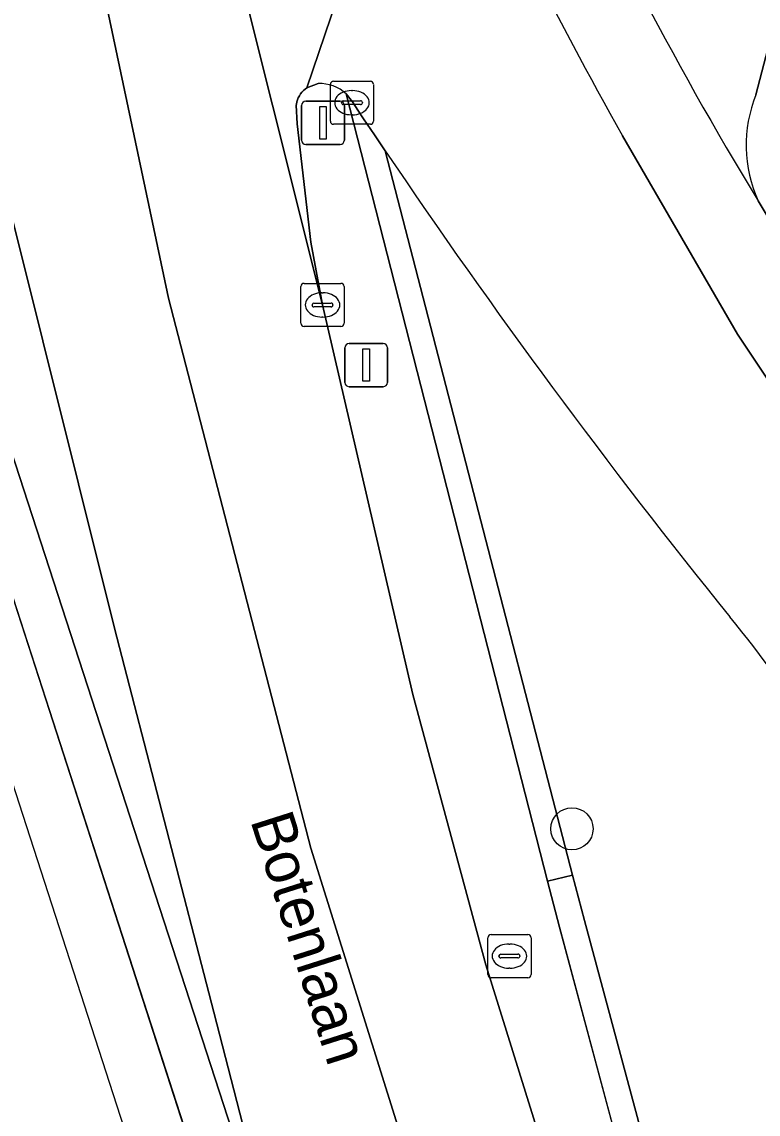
# Model space of a CAD drawing. Extents: x 159371 to 159986, y 382987 to 383597.
# Drawn here: x 159398.33 to 159415.41, y 383308.31 to 383333.62 of the extents above; entities that cross this region are included whole.
import ezdxf

# ---------------------------------------------------------------- set-up
doc = ezdxf.new("R2010")
doc.units = 0
for name, color, linetype in [('IMGEO_Berm_groen', 7, 'Continuous'), ('IMGEO_Boom', 7, 'Continuous'), ('IMGEO_Fietspad_open', 7, 'Continuous'), ('IMGEO_Groenvoorziening', 7, 'Continuous'), ('IMGEO_Haag', 7, 'Continuous'), ('IMGEO_Kolk', 7, 'Continuous'), ('IMGEO_Lichtmast', 7, 'Continuous'), ('IMGEO_Openbare_ruimte_label', 7, 'Continuous'), ('IMGEO_Rijbaan_lokaal_open', 7, 'Continuous'), ('IMGEO_Rijbaan_regionaal_gesloten', 7, 'Continuous'), ('IMGEO_Rioolput', 7, 'Continuous'), ('IMGEO_Verkeersbordpaal', 7, 'Continuous'), ('IMGEO_Verkeerseiland_gesloten', 7, 'Continuous'), ('IMGEO_Verkeerseiland_groen', 7, 'Continuous')]:
    doc.layers.add(name, color=color, linetype=linetype)

msp = doc.modelspace()

# ---------------------------------------------------------------- linework, layer by layer
at = {"layer": 'IMGEO_Berm_groen'}
for points in [[(159405.206, 383332.192), (159404.942, 383332.097), (159404.901, 383332.066), (159404.863, 383332.032), (159404.828, 383331.995), (159404.796, 383331.954), (159404.768, 383331.911), (159404.744, 383331.866), (159404.725, 383331.818), (159404.709, 383331.769), (159404.698, 383331.719), (159404.694, 383331.691), (159404.715, 383331.26), (159405.034, 383328.516), (159405.305, 383327.063), (159407.402, 383318.032), (159409.091, 383311.769), (159411.115, 383305.269), (159412.518, 383300.689), (159415.124, 383292.413), (159421.088, 383273.781)], [(159435.017, 383236.267), (159430.413, 383250.521), (159413.5, 383303.035), (159412.414, 383306.629), (159410.796, 383312.64), (159410.522, 383313.711), (159405.852, 383331.954)], [(159406.761, 383330.631), (159408.577, 383323.612), (159411.104, 383313.847), (159411.376, 383312.794), (159412.992, 383306.793), (159414.072, 383303.213), (159430.983, 383250.705), (159435.589, 383236.441), (159472.722, 383122.014), (159492.238, 383063.663), (159493.793, 383059.366), (159494.626, 383071.478), (159494.813, 383074.201), (159494.983, 383076.684), (159494.993, 383077.003)]]:
    msp.add_lwpolyline(points, dxfattribs=at)
for centre, radius, start, end in [((159405.255, 383331.329), 0.864, 46.3029, 93.2474), ((159540.355, 383421.071), 161.328, 214.09704, 218.86798), ((159394.275, 383302.805), 26.627, 24.4699, 39.7553)]:
    msp.add_arc(centre, radius, start, end, dxfattribs=at)
at = {"layer": 'IMGEO_Boom'}
msp.add_circle((159411.088, 383314.922), 0.489, dxfattribs=at)
at = {"layer": 'IMGEO_Fietspad_open'}
for points in [[(159412.263, 383330.985), (159414.927, 383326.382), (159415.744, 383325.156), (159419.36, 383320.289), (159420.855, 383318.04)], [(159422.415, 383319.283), (159417.233, 383326.485), (159417.087, 383326.688), (159415.406, 383329.473)]]:
    msp.add_lwpolyline(points, dxfattribs=at)
for centre, radius, start, end in [((159489.397, 383374.406), 86.566, 203.62917, 211.26927), ((159487.582, 383373.724), 86.6, 203.26224, 209.57217)]:
    msp.add_arc(centre, radius, start, end, dxfattribs=at)
at = {"layer": 'IMGEO_Groenvoorziening'}
for points in [[(159406.761, 383330.631), (159406.509, 383331.005), (159406.258, 383331.379), (159406.127, 383331.575), (159405.997, 383331.771), (159405.852, 383331.954), (159410.522, 383313.711), (159411.104, 383313.847), (159408.577, 383323.612)], [(159472.722, 383122.014), (159435.589, 383236.441), (159430.983, 383250.705), (159414.072, 383303.213), (159412.992, 383306.793), (159411.376, 383312.794), (159411.104, 383313.847), (159410.522, 383313.711), (159410.796, 383312.64), (159412.414, 383306.629), (159413.5, 383303.035), (159430.413, 383250.521), (159435.017, 383236.267), (159472.152, 383121.826), (159491.672, 383063.465), (159493.69, 383057.889), (159493.717, 383058.243), (159493.743, 383058.624), (159493.793, 383059.366), (159492.238, 383063.663)]]:
    msp.add_lwpolyline(points, close=True, dxfattribs=at)
at = {"layer": 'IMGEO_Haag'}
for points in [[(159408.577, 383323.612), (159406.761, 383330.631), (159406.509, 383331.005), (159406.258, 383331.379), (159406.127, 383331.575), (159405.997, 383331.771), (159405.852, 383331.954), (159410.522, 383313.711), (159411.104, 383313.847)], [(159430.983, 383250.705), (159414.072, 383303.213), (159412.992, 383306.793), (159411.376, 383312.794), (159411.104, 383313.847), (159410.522, 383313.711), (159410.796, 383312.64), (159412.414, 383306.629), (159413.5, 383303.035), (159430.413, 383250.521), (159435.017, 383236.267), (159472.152, 383121.826), (159491.672, 383063.465), (159493.69, 383057.889), (159493.717, 383058.243), (159493.743, 383058.624), (159493.793, 383059.366), (159492.238, 383063.663), (159472.722, 383122.014), (159435.589, 383236.441)]]:
    msp.add_lwpolyline(points, close=True, dxfattribs=at)
at = {"layer": 'IMGEO_Kolk'}
for p, q in [((159405.487, 383331.324), (159405.487, 383332.176)), ((159405.562, 383332.25), (159406.414, 383332.25)), ((159406.488, 383332.176), (159406.488, 383331.324)), ((159405.975, 383332.03), (159406, 383332.03)), ((159405.746, 383331.744), (159405.746, 383331.756)), ((159406.184, 383331.707), (159405.786, 383331.707)), ((159405.789, 383331.793), (159406.187, 383331.793)), ((159406.23, 383331.756), (159406.23, 383331.744)), ((159405.998, 383331.47), (159405.973, 383331.47)), ((159406.414, 383331.25), (159405.562, 383331.25)), ((159404.88, 383327.563), (159405.732, 383327.563)), ((159404.805, 383326.637), (159404.805, 383327.489)), ((159405.293, 383327.343), (159405.318, 383327.343)), ((159405.806, 383327.489), (159405.806, 383326.637)), ((159405.064, 383327.057), (159405.064, 383327.069)), ((159405.107, 383327.106), (159405.505, 383327.106)), ((159405.548, 383327.069), (159405.548, 383327.057)), ((159405.502, 383327.02), (159405.104, 383327.02)), ((159405.732, 383326.563), (159404.88, 383326.563)), ((159405.316, 383326.783), (159405.291, 383326.783))]:
    msp.add_line(p, q, dxfattribs=at)
for points in [[(159405.487, 383331.324), (159405.487, 383332.176)], [(159405.562, 383332.25), (159406.414, 383332.25)], [(159406.488, 383332.176), (159406.488, 383331.324)], [(159406.414, 383331.25), (159405.562, 383331.25)], [(159404.88, 383327.563), (159405.732, 383327.563)], [(159404.805, 383326.637), (159404.805, 383327.489)], [(159405.806, 383327.489), (159405.806, 383326.637)], [(159405.732, 383326.563), (159404.88, 383326.563)]]:
    msp.add_lwpolyline(points, dxfattribs=at)
for centre, radius, start, end in [((159405.564, 383332.174), 0.0765, 91.552, 178.448), ((159405.564, 383332.174), 0.0765, 91.552, 178.448), ((159406.412, 383332.174), 0.0765, 1.552, 88.448), ((159406.412, 383332.174), 0.0765, 1.552, 88.448), ((159405.786, 383331.753), 0.0403, 85.8775, 175.7526), ((159405.783, 383331.743), 0.0366, 178.938, 274.7102), ((159406.187, 383331.75), 0.043, 264.8664, 352.4533), ((159406.191, 383331.755), 0.0386, 1.7309, 96.639), ((159405.564, 383331.326), 0.0765, 181.552, 268.448), ((159405.564, 383331.326), 0.0765, 181.552, 268.448), ((159406.412, 383331.326), 0.0765, 271.552, 358.448), ((159406.412, 383331.326), 0.0765, 271.552, 358.448), ((159404.882, 383327.487), 0.0765, 91.552, 178.448), ((159404.882, 383327.487), 0.0765, 91.552, 178.448), ((159405.73, 383327.487), 0.0765, 1.552, 88.448), ((159405.73, 383327.487), 0.0765, 1.552, 88.448), ((159405.104, 383327.066), 0.0403, 85.8775, 175.7526), ((159405.101, 383327.056), 0.0366, 178.938, 274.7102), ((159405.505, 383327.063), 0.043, 264.8664, 352.4533), ((159405.509, 383327.068), 0.0386, 1.7309, 96.639), ((159404.882, 383326.639), 0.0765, 181.552, 268.448), ((159404.882, 383326.639), 0.0765, 181.552, 268.448), ((159405.73, 383326.639), 0.0765, 271.552, 358.448), ((159405.73, 383326.639), 0.0765, 271.552, 358.448)]:
    msp.add_arc(centre, radius, start, end, dxfattribs=at)
for centre, major_axis, ratio, start_param, end_param in [((159405.974, 383331.75), (-0.387, 0.002), 0.722429, 4.712389, 7.853982), ((159405.999, 383331.75), (-0.39, 0.002), 0.717154, 1.570796, 4.712389), ((159405.292, 383327.063), (-0.387, 0.002), 0.722429, 4.712389, 7.853982), ((159405.317, 383327.063), (-0.39, 0.002), 0.717154, 1.570796, 4.712389)]:
    msp.add_ellipse(centre, major_axis=major_axis, ratio=ratio, start_param=start_param, end_param=end_param, dxfattribs=at)
at = {"layer": 'IMGEO_Lichtmast'}
for p, q in [((159405.822, 383325.269), (159405.822, 383326.069)), ((159405.822, 383326.069), (159405.822, 383325.269)), ((159405.922, 383326.169), (159406.712, 383326.169)), ((159406.712, 383326.169), (159405.922, 383326.169)), ((159406.812, 383326.069), (159406.812, 383325.269)), ((159406.812, 383325.269), (159406.812, 383326.069)), ((159406.712, 383325.169), (159405.922, 383325.169)), ((159405.922, 383325.169), (159406.712, 383325.169))]:
    msp.add_line(p, q, dxfattribs=at)
msp.add_lwpolyline([(159406.242, 383326.044), (159406.392, 383326.044), (159406.392, 383325.294), (159406.242, 383325.294), (159406.242, 383326.044)], dxfattribs=at)
for centre, start, end in [((159405.922, 383326.069), 90, 180), ((159405.922, 383326.069), 90, 180), ((159406.712, 383326.069), 0, 90), ((159406.712, 383326.069), 360, 90), ((159405.922, 383325.269), 180, 270), ((159405.922, 383325.269), 180, 270), ((159406.712, 383325.269), 270, 0), ((159406.712, 383325.269), 270, 0)]:
    msp.add_arc(centre, 0.1, start, end, dxfattribs=at)
at = {"layer": 'IMGEO_Rijbaan_lokaal_open'}
for points in [[(159407.29, 383339.017), (159404.942, 383332.097), (159405.206, 383332.192)], [(159415.352, 383331.935), (159415.872, 383333.917)], [(159405.852, 383331.954), (159405.997, 383331.771), (159406.127, 383331.575), (159406.258, 383331.379), (159406.509, 383331.005), (159406.761, 383330.631)], [(159420.855, 383318.04), (159419.36, 383320.289), (159415.744, 383325.156), (159414.927, 383326.382), (159412.263, 383330.985)]]:
    msp.add_lwpolyline(points, dxfattribs=at)
for centre, radius, start, end in [((159489.397, 383374.406), 86.566, 203.62917, 211.26927), ((159487.582, 383373.724), 86.6, 203.26224, 209.57217), ((159405.255, 383331.329), 0.864, 46.3029, 93.2474), ((159418.26, 383330.767), 3.133, 158.117, 204.396), ((159540.355, 383421.071), 161.328, 214.09704, 218.86798), ((159394.275, 383302.805), 26.627, 24.4699, 39.7553)]:
    msp.add_arc(centre, radius, start, end, dxfattribs=at)
at = {"layer": 'IMGEO_Rijbaan_regionaal_gesloten'}
for points in [[(159421.088, 383273.781), (159415.124, 383292.413), (159412.518, 383300.689), (159411.115, 383305.269), (159409.091, 383311.769), (159407.402, 383318.032), (159405.305, 383327.063), (159401.833, 383340.927), (159398.684, 383357.88), (159394.285, 383385.736), (159393.91, 383388.103), (159391.102, 383386.058), (159392.136, 383379.485), (159394.586, 383364.232), (159396.636, 383352.03), (159398.985, 383340.227), (159401.734, 383327.224), (159405.034, 383314.472), (159415.383, 383281.415), (159427.53, 383243.457)], [(159427.53, 383243.457), (159415.383, 383281.415), (159405.034, 383314.472), (159401.734, 383327.224), (159398.985, 383340.227), (159396.636, 383352.03), (159394.586, 383364.232), (159392.136, 383379.485), (159391.102, 383386.058), (159388.33, 383384.04), (159390.536, 383370.136), (159392.585, 383357.932), (159394.485, 383347.33), (159396.084, 383339.028), (159397.984, 383329.576), (159400.483, 383319.573), (159402.783, 383310.671), (159404.584, 383303.68), (159421.962, 383250)], [(159397.983, 383323.994), (159404.584, 383303.68), (159402.783, 383310.671), (159400.483, 383319.573), (159397.984, 383329.576), (159396.084, 383339.028), (159394.485, 383347.33), (159392.585, 383357.932), (159390.536, 383370.136), (159388.33, 383384.04)], [(159398.684, 383357.88), (159401.833, 383340.927), (159405.305, 383327.063), (159405.034, 383328.516), (159404.715, 383331.26), (159404.694, 383331.691), (159404.698, 383331.719), (159404.709, 383331.769), (159404.725, 383331.818), (159404.744, 383331.866), (159404.768, 383331.911), (159404.796, 383331.954), (159404.828, 383331.995), (159404.863, 383332.032), (159404.901, 383332.066), (159404.942, 383332.097), (159407.29, 383339.017), (159407.157, 383339.182), (159406.351, 383340.537), (159405.493, 383342.287), (159404.796, 383344.107), (159404.263, 383345.982), (159403.9, 383347.897), (159401.71, 383358.95)]]:
    msp.add_lwpolyline(points, dxfattribs=at)
msp.add_lwpolyline([(159490.911, 383018.958), (159492.331, 383019.511), (159488.26, 383035.08), (159486.225, 383042.864), (159485.163, 383046.926), (159484.195, 383050.627), (159483.228, 383054.328), (159481.958, 383059.184), (159480.897, 383062.863), (159477.465, 383074.388), (159474.861, 383082.723), (159471.482, 383093.553), (159456.598, 383139.574), (159432.844, 383213.007), (159426.147, 383233.702), (159420.872, 383250), (159392.563, 383337.471), (159379.438, 383378.025), (159378.284, 383377.139), (159419.119, 383251.193), (159440.169, 383186.271), (159452.968, 383146.401), (159478.754, 383066.077)], close=True, dxfattribs=at)
at = {"layer": 'IMGEO_Rioolput'}
for p, q in [((159409.138, 383311.545), (159409.138, 383312.397)), ((159409.213, 383312.471), (159410.065, 383312.471)), ((159410.139, 383312.397), (159410.139, 383311.545)), ((159409.626, 383312.251), (159409.651, 383312.251)), ((159409.397, 383311.965), (159409.397, 383311.977)), ((159409.835, 383311.928), (159409.437, 383311.928)), ((159409.44, 383312.014), (159409.838, 383312.014)), ((159409.881, 383311.977), (159409.881, 383311.965)), ((159409.649, 383311.691), (159409.624, 383311.691)), ((159410.065, 383311.471), (159409.213, 383311.471))]:
    msp.add_line(p, q, dxfattribs=at)
for points in [[(159409.138, 383311.545), (159409.138, 383312.397)], [(159409.213, 383312.471), (159410.065, 383312.471)], [(159410.139, 383312.397), (159410.139, 383311.545)], [(159410.065, 383311.471), (159409.213, 383311.471)]]:
    msp.add_lwpolyline(points, dxfattribs=at)
for centre, radius, start, end in [((159409.215, 383312.395), 0.0765, 91.552, 178.448), ((159409.215, 383312.395), 0.0765, 91.552, 178.448), ((159410.063, 383312.395), 0.0765, 1.552, 88.448), ((159410.063, 383312.395), 0.0765, 1.552, 88.448), ((159409.437, 383311.974), 0.0403, 85.8775, 175.7526), ((159409.434, 383311.964), 0.0366, 178.938, 274.7102), ((159409.838, 383311.971), 0.043, 264.8664, 352.4533), ((159409.842, 383311.976), 0.0386, 1.7309, 96.639), ((159409.215, 383311.547), 0.0765, 181.552, 268.448), ((159409.215, 383311.547), 0.0765, 181.552, 268.448), ((159410.063, 383311.547), 0.0765, 271.552, 358.448), ((159410.063, 383311.547), 0.0765, 271.552, 358.448)]:
    msp.add_arc(centre, radius, start, end, dxfattribs=at)
for centre, major_axis, ratio, start_param, end_param in [((159409.625, 383311.971), (-0.387, 0.002), 0.722429, 4.712389, 7.853982), ((159409.65, 383311.971), (-0.39, 0.002), 0.717154, 1.570796, 4.712389)]:
    msp.add_ellipse(centre, major_axis=major_axis, ratio=ratio, start_param=start_param, end_param=end_param, dxfattribs=at)
at = {"layer": 'IMGEO_Verkeersbordpaal'}
for p, q in [((159404.821, 383330.884), (159404.821, 383331.684)), ((159404.821, 383331.684), (159404.821, 383330.884)), ((159404.921, 383331.784), (159405.711, 383331.784)), ((159405.711, 383331.784), (159404.921, 383331.784)), ((159405.811, 383331.684), (159405.811, 383330.884)), ((159405.811, 383330.884), (159405.811, 383331.684)), ((159405.711, 383330.784), (159404.921, 383330.784)), ((159404.921, 383330.784), (159405.711, 383330.784))]:
    msp.add_line(p, q, dxfattribs=at)
msp.add_lwpolyline([(159405.241, 383331.659), (159405.391, 383331.659), (159405.391, 383330.909), (159405.241, 383330.909), (159405.241, 383331.659)], dxfattribs=at)
for centre, start, end in [((159404.921, 383331.684), 90, 180), ((159404.921, 383331.684), 90, 180), ((159405.711, 383331.684), 0, 90), ((159405.711, 383331.684), 360, 90), ((159404.921, 383330.884), 180, 270), ((159404.921, 383330.884), 180, 270), ((159405.711, 383330.884), 270, 0), ((159405.711, 383330.884), 270, 0)]:
    msp.add_arc(centre, 0.1, start, end, dxfattribs=at)
at = {"layer": 'IMGEO_Verkeerseiland_gesloten'}
for points in [[(159394.792, 383335.502), (159394.211, 383337.976), (159392.261, 383346.286), (159390.608, 383353.724), (159389.498, 383359.007), (159388.128, 383365.883), (159386.559, 383374.771), (159385.35, 383381.87), (159379.438, 383378.025), (159392.563, 383337.471), (159420.872, 383250), (159426.147, 383233.702), (159432.844, 383213.007), (159456.598, 383139.574), (159471.482, 383093.553)], [(159472.482, 383093.792), (159457.577, 383139.944), (159433.835, 383213.326), (159427.145, 383233.992), (159421.962, 383250), (159404.584, 383303.68), (159397.983, 383323.994)]]:
    msp.add_lwpolyline(points, dxfattribs=at)
at = {"layer": 'IMGEO_Verkeerseiland_groen'}
for points in [[(159415.872, 383333.917), (159415.352, 383331.935)], [(159415.406, 383329.473), (159417.087, 383326.688), (159417.233, 383326.485)]]:
    msp.add_lwpolyline(points, dxfattribs=at)
msp.add_arc((159418.26, 383330.767), 3.133, 158.117, 204.396, dxfattribs=at)

# ---------------------------------------------------------------- texts
at = {"layer": 'IMGEO_Openbare_ruimte_label'}
msp.add_text('Botenlaan', height=1, rotation=287.6377, dxfattribs=at).set_placement((159403.625, 383315.12))

doc.saveas('drawing.dxf')
